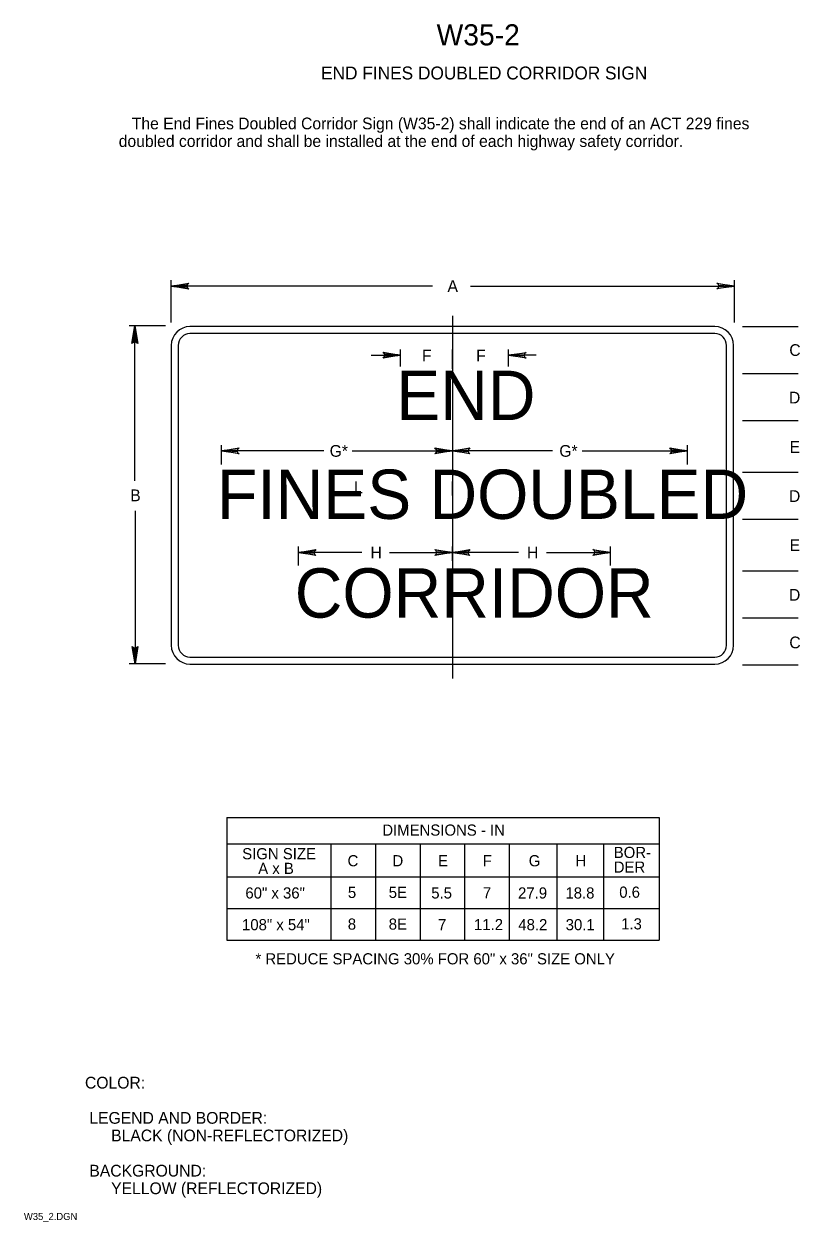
# Model space of a CAD drawing. Extents: x 0.012 to 0.178, y 0.004 to 0.259.
import ezdxf

# ---------------------------------------------------------------- set-up
doc = ezdxf.new("R2010")
doc.units = 0
for name, color, linetype in [('1', 7, 'Continuous'), ('2', 7, 'Continuous'), ('3', 7, 'Continuous')]:
    doc.layers.add(name, color=color, linetype=linetype)

# ---------------------------------------------------------------- blocks, each defined once
blk = doc.blocks.new('RARROW')
at = {"layer": '3'}
for p, q in [((-2.156, 0.285), (-2.2665, 0.384625)), ((-2.2665, 0.384625), (0, 0)), ((0, 0), (-2.2665, -0.379125)), ((-2.156, 0.285), (-2.075625, 0.12075)), ((0, 0), (-2.156, 0.285)), ((-2.14975, -0.2705), (0, 0)), ((-2.075625, 0.12075), (0, 0)), ((0, 0), (-2.074, -0.108)), ((-2.2665, -0.379125), (-2.14975, -0.2705)), ((-2.074, -0.108), (-2.14975, -0.2705))]:
    blk.add_line(p, q, dxfattribs=at)

msp = doc.modelspace()

# ---------------------------------------------------------------- linework, layer by layer
at = {"layer": '1'}
msp.add_line((0.10364, 0.1969), (0.10364, 0.1197), dxfattribs=at)
at = {"layer": '3'}
for p, q in [((0.04375, 0.1955), (0.04375, 0.2045)), ((0.16375, 0.1955), (0.16375, 0.2045)), ((0.09942, 0.20325), (0.04375, 0.20325)), ((0.10749, 0.20325), (0.16375, 0.20325)), ((0.0425, 0.19478), (0.03477, 0.19478)), ((0.03537, 0.191), (0.036, 0.19475)), ((0.036, 0.19475), (0.03553, 0.19118)), ((0.0358, 0.19132), (0.036, 0.19475)), ((0.036, 0.19475), (0.03618, 0.19132)), ((0.03644, 0.19119), (0.036, 0.19475)), ((0.036, 0.19475), (0.03662, 0.191)), ((0.036, 0.16176), (0.036, 0.19475)), ((0.15953, 0.19462), (0.04775, 0.19462)), ((0.1654, 0.19462), (0.17728, 0.19462)), ((0.15953, 0.19312), (0.04775, 0.19312)), ((0.03553, 0.19118), (0.03537, 0.191)), ((0.03553, 0.19118), (0.0358, 0.19132)), ((0.03618, 0.19132), (0.03644, 0.19119)), ((0.03662, 0.191), (0.03644, 0.19119)), ((0.04375, 0.19062), (0.04375, 0.12675)), ((0.04525, 0.19062), (0.04525, 0.12675)), ((0.09262, 0.18612), (0.09262, 0.18977)), ((0.10364, 0.18564), (0.10364, 0.18977)), ((0.1156, 0.18612), (0.1156, 0.18977)), ((0.16203, 0.12675), (0.16203, 0.19062)), ((0.16353, 0.12675), (0.16353, 0.19062)), ((0.08637, 0.18852), (0.09262, 0.18852)), ((0.12146, 0.18852), (0.11559, 0.18852)), ((0.1654, 0.18463), (0.17728, 0.18463)), ((0.1654, 0.17463), (0.17728, 0.17463)), ((0.05445, 0.16526), (0.05445, 0.1694)), ((0.1537, 0.16526), (0.1537, 0.1694)), ((0.07626, 0.16815), (0.05445, 0.16815)), ((0.08231, 0.16815), (0.10364, 0.16815)), ((0.12493, 0.16815), (0.10364, 0.16815)), ((0.13129, 0.16815), (0.1537, 0.16815)), ((0.1654, 0.16362), (0.17728, 0.16362)), ((0.10364, 0.15864), (0.10364, 0.16164)), ((0.03604, 0.15539), (0.03604, 0.12278)), ((0.1654, 0.15363), (0.17728, 0.15363)), ((0.07083, 0.14374), (0.07083, 0.14777)), ((0.08432, 0.14652), (0.07083, 0.14652)), ((0.09026, 0.14652), (0.10364, 0.14652)), ((0.10364, 0.14477), (0.10364, 0.14777)), ((0.11774, 0.14652), (0.10364, 0.14652)), ((0.12369, 0.14652), (0.13734, 0.14652)), ((0.13734, 0.14374), (0.13734, 0.14777)), ((0.1654, 0.14263), (0.17728, 0.14263)), ((0.1654, 0.13262), (0.17728, 0.13262)), ((0.0425, 0.12278), (0.03477, 0.12278)), ((0.04775, 0.12425), (0.15953, 0.12425)), ((0.04775, 0.12275), (0.15953, 0.12275)), ((0.1654, 0.12262), (0.17728, 0.12262)), ((0.05562, 0.09006), (0.05562, 0.06393)), ((0.05562, 0.09006), (0.14771, 0.09006)), ((0.14771, 0.09006), (0.14771, 0.06393)), ((0.14771, 0.08443), (0.05562, 0.08443)), ((0.07775, 0.08443), (0.07775, 0.06393)), ((0.08725, 0.08443), (0.08725, 0.06393)), ((0.09675, 0.08443), (0.09675, 0.06393)), ((0.10625, 0.08443), (0.10625, 0.06393)), ((0.11575, 0.08443), (0.11575, 0.06393)), ((0.12589, 0.08443), (0.12589, 0.06393)), ((0.1358, 0.08443), (0.1358, 0.06393)), ((0.05562, 0.07743), (0.14771, 0.07743)), ((0.05562, 0.07068), (0.14771, 0.07068)), ((0.05562, 0.06393), (0.14771, 0.06393))]:
    msp.add_line(p, q, dxfattribs=at)
for centre, radius, start, end in [((0.04775, 0.19062), 0.004, 90, 180), ((0.15953, 0.19062), 0.004, 0, 90), ((0.04775, 0.19062), 0.0025, 90, 180), ((0.15953, 0.19062), 0.0025, 0, 90), ((0.04775, 0.12675), 0.004, 180, 270), ((0.04775, 0.12675), 0.0025, 180, 270), ((0.15953, 0.12675), 0.004, 270, 0), ((0.15953, 0.12675), 0.0025, 270, 0)]:
    msp.add_arc(centre, radius, start, end, dxfattribs=at)

# ---------------------------------------------------------------- block references
at = {"layer": '3', "xscale": 0.0016545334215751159, "yscale": 0.0016366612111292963}
for p, rotation in [((0.04375, 0.20325), 180), ((0.11559, 0.18852), 180), ((0.05445, 0.16815), 180), ((0.10364, 0.16815), 180), ((0.07083, 0.14652), 180), ((0.10364, 0.14652), 180), ((0.03604, 0.12278), -90)]:
    msp.add_blockref('RARROW', p, dxfattribs=dict(at, rotation=rotation))
for p in [(0.16375, 0.20325), (0.09262, 0.18852), (0.10364, 0.16815), (0.1537, 0.16815), (0.10364, 0.14652), (0.13734, 0.14652)]:
    msp.add_blockref('RARROW', p, dxfattribs=at)

# ---------------------------------------------------------------- texts
at = {"layer": '1'}
for s, height, p in [('W35-2', 0.0045, (0.10028, 0.2545)), ('END FINES DOUBLED CORRIDOR SIGN', 0.0027503, (0.07567, 0.24725)), ('COLOR:', 0.0025, (0.02538, 0.03237)), (' LEGEND AND BORDER:', 0.0024998, (0.02538, 0.02487)), ('      BLACK (NON-REFLECTORIZED)', 0.0024998, (0.02538, 0.02113)), (' BACKGROUND:', 0.0024998, (0.02538, 0.01363)), ('      YELLOW (REFLECTORIZED)', 0.0024998, (0.02538, 0.00988)), ('W35_2.DGN', 0.0015, (0.01238, 0.00438))]:
    msp.add_text(s, height=height, dxfattribs=at).set_placement(p)
at = {"layer": '2'}
for s, p in [('   The End Fines Doubled Corridor Sign (W35-2) shall indicate the end of an ACT 229 fines ', (0.03257, 0.23663)), ('doubled corridor and shall be installed at the end of each highway safety corridor.', (0.03257, 0.23288))]:
    msp.add_text(s, height=0.0024998, dxfattribs=at).set_placement(p)
at = {"layer": '3'}
for s, height, p in [('A', 0.0025, (0.1026, 0.202)), ('F', 0.0025, (0.09716, 0.18721)), ('F', 0.0025, (0.10871, 0.1872)), ('C', 0.0025, (0.17541, 0.18837)), ('END', 0.0105, (0.09169, 0.17473)), ('D', 0.0025, (0.17533, 0.17825)), ('G*', 0.0025, (0.0775, 0.1669)), ('G*', 0.0025, (0.12642, 0.1669)), ('E', 0.0025, (0.17547, 0.16774)), ('FINES DOUBLED', 0.0105, (0.05352, 0.15367)), ('L', 0.0025, (0.08269, 0.15914)), ('B', 0.0025, (0.03502, 0.15744)), ('D', 0.0025, (0.17533, 0.15728)), ('E', 0.0025, (0.17547, 0.14682)), ('H', 0.0025, (0.0862, 0.14527)), ('H', 0.0025, (0.11954, 0.14527)), ('CORRIDOR', 0.0105, (0.07007, 0.13265)), ('D', 0.0025, (0.17533, 0.13625)), ('C', 0.0025, (0.17541, 0.12611)), ('DIMENSIONS - IN', 0.0023752, (0.08871, 0.08622)), ('SIGN SIZE', 0.002375, (0.05887, 0.08119)), ('C', 0.00238, (0.08131, 0.07969)), ('D', 0.00238, (0.09088, 0.07969)), ('E', 0.00238, (0.10059, 0.07969)), ('F', 0.00238, (0.1101, 0.07969)), ('G', 0.00238, (0.1199, 0.07969)), ('H', 0.00238, (0.12983, 0.07969)), ('BOR-', 0.002375, (0.13801, 0.08146)), ('A x B', 0.002375, (0.06228, 0.07806)), ('DER', 0.002375, (0.13801, 0.07834)), ('60" x 36"', 0.002375, (0.05955, 0.07283)), ('5', 0.00238, (0.08138, 0.07295)), ('5E', 0.002375, (0.09008, 0.07295)), ('5.5', 0.002375, (0.09914, 0.07283)), ('7', 0.00238, (0.11014, 0.07285)), ('27.9', 0.002375, (0.11763, 0.07283)), ('18.8', 0.002375, (0.12772, 0.07283)), ('0.6', 0.002375, (0.13918, 0.073)), ('108" x 54"', 0.002375, (0.05883, 0.06608)), ('8', 0.00238, (0.08136, 0.0662)), ('8E', 0.002375, (0.09008, 0.0662)), ('7', 0.00238, (0.10058, 0.06608)), ('11.2', 0.002375, (0.10825, 0.0661)), ('48.2', 0.002375, (0.11768, 0.06608)), ('30.1', 0.002375, (0.12777, 0.06608)), ('1.3', 0.002375, (0.13958, 0.06625)), ('* REDUCE SPACING 30% FOR 60" x 36" SIZE ONLY', 0.0023752, (0.06169, 0.05881))]:
    msp.add_text(s, height=height, dxfattribs=at).set_placement(p)

doc.saveas('drawing.dxf')
